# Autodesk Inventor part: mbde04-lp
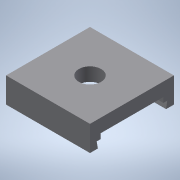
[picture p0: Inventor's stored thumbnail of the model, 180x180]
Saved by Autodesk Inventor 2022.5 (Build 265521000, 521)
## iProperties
Created: 2016-12
Part Number: mbde04-lp
Material: 一般
Document SubType Name: Modeling
Designer: imaocorp
Density: 1 g/cm^3
Appearance: 既定
Author: imaocorp
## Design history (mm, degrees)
node "mbde04-lp.x_t1"
node "160143"
node "Base1"
